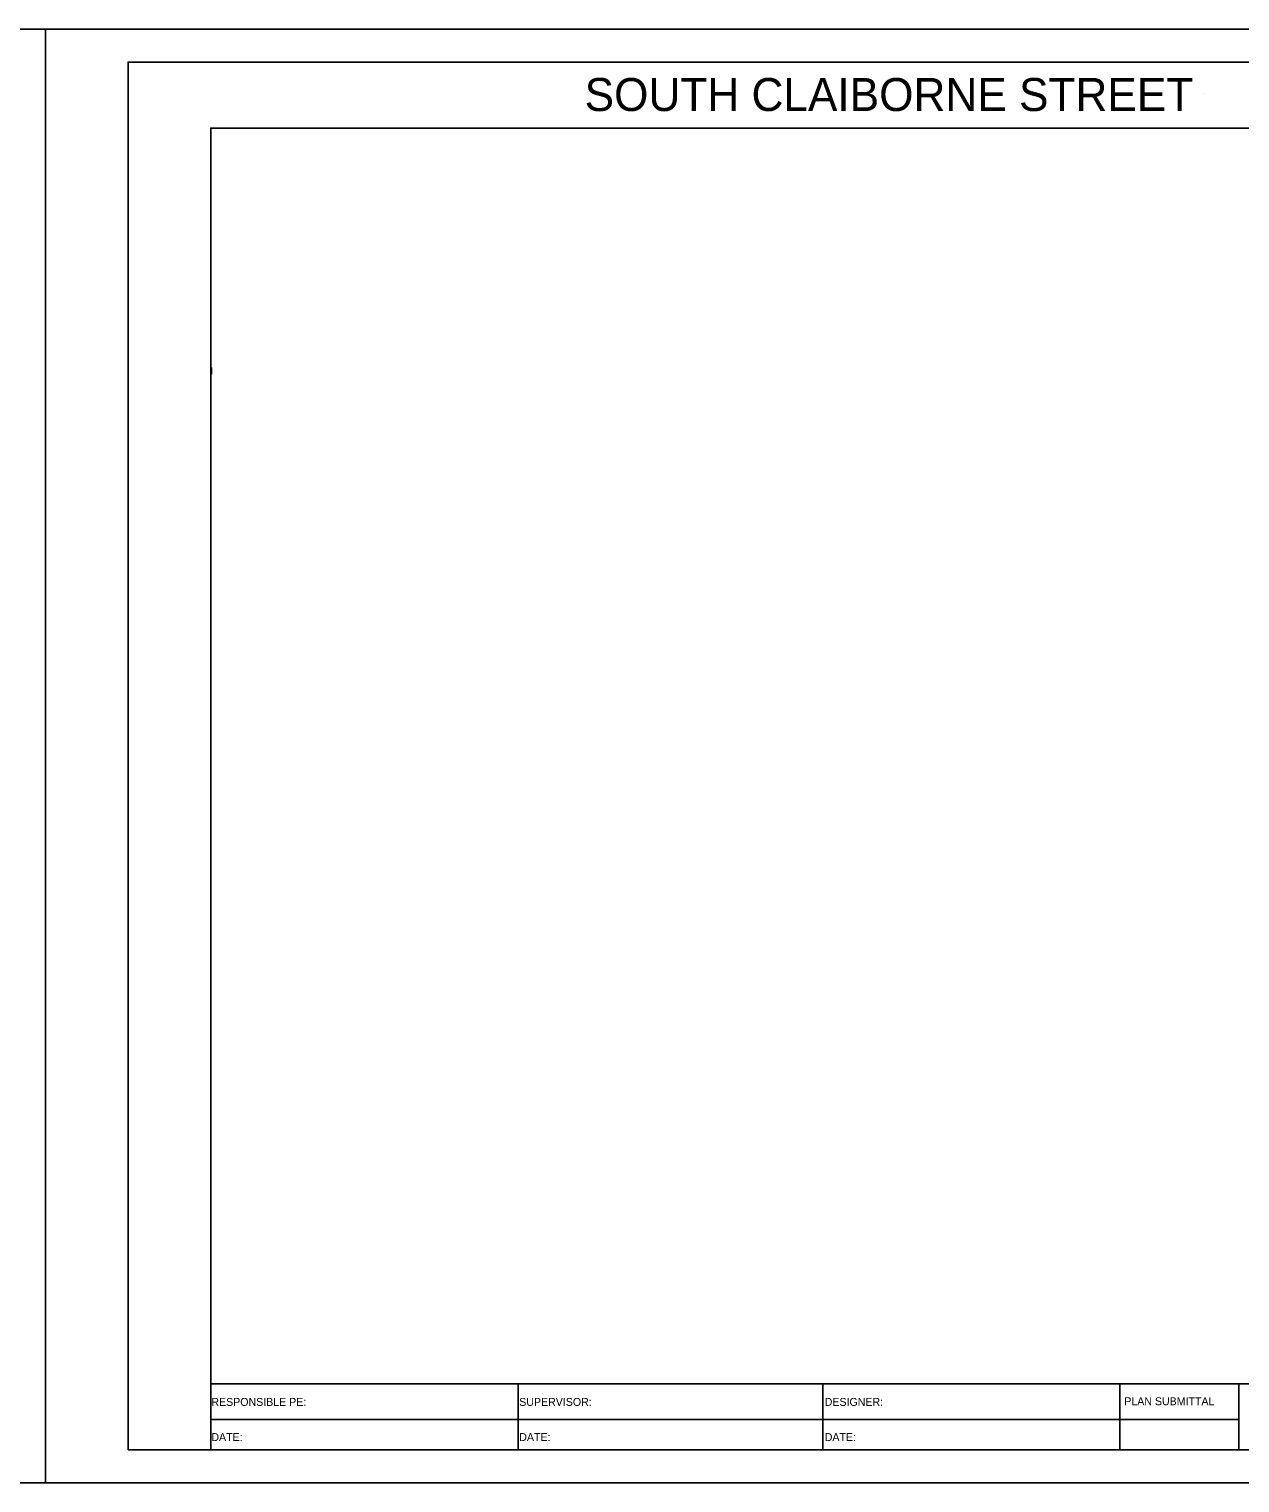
# Model space of a CAD drawing. Extents: x 1797478 to 1803816, y 246529 to 250952.
# Drawn here: x 1803133.5 to 1803316.8, y 250064.4 to 250284.4 of the extents above; entities that cross this region are included whole.
import ezdxf

# ---------------------------------------------------------------- set-up
doc = ezdxf.new("R2010")
doc.units = 0
for name, color, linetype in [('2', 7, 'Continuous'), ('ANNO-SHT', 7, 'Continuous'), ('ANNO-TXT', 7, 'Continuous'), ('AXIS', 7, 'Continuous'), ('DRAINAGE', 7, 'Continuous'), ('Level 1', 7, 'Continuous'), ('Level 62', 7, 'Continuous'), ('SHT-BDR', 7, 'Continuous'), ('SHT-BNDRY', 7, 'Continuous')]:
    doc.layers.add(name, color=color, linetype=linetype)

# ---------------------------------------------------------------- blocks, each defined once
blk = doc.blocks.new('SC47208')
at = {"layer": 'Level 1'}
blk.add_line((0, 0), (0, 0), dxfattribs=at)

msp = doc.modelspace()

# ---------------------------------------------------------------- linework, layer by layer
at = {"layer": '2'}
msp.add_lwpolyline([(1803161.12, 250233.21), (1803161.1, 250232.21)], dxfattribs=at)
msp.add_lwpolyline([(1803161.12, 250233.21), (1803161.1, 250232.21)], dxfattribs=at)
at = {"layer": 'AXIS'}
msp.add_line((1803161, 250189.42), (1803161, 250189.43), dxfattribs=at)
at = {"layer": 'Level 62'}
for points in [[(1802796, 250064.42), (1803136, 250064.42), (1803136, 250284.42), (1802796, 250284.42)], [(1803136, 250064.42), (1803476, 250064.42), (1803476, 250284.42), (1803136, 250284.42)]]:
    msp.add_lwpolyline(points, close=True, dxfattribs=at)
at = {"layer": 'SHT-BDR'}
msp.add_lwpolyline([(1803161, 250079.43), (1803461, 250079.43), (1803461, 250269.43), (1803161, 250269.43)], close=True, dxfattribs=at)
at = {"layer": 'SHT-BNDRY'}
for p, q in [((1803161, 250069.42), (1803161, 250079.43)), ((1803207.52, 250079.43), (1803207.52, 250069.42)), ((1803253.67, 250069.42), (1803253.67, 250079.43)), ((1803298.59, 250069.42), (1803298.59, 250079.43)), ((1803316.63, 250069.42), (1803316.63, 250079.43)), ((1803161, 250074.03), (1803316.63, 250074.03))]:
    msp.add_line(p, q, dxfattribs=at)
msp.add_lwpolyline([(1803148.5, 250069.42), (1803471, 250069.42), (1803471, 250279.42), (1803148.5, 250279.42)], close=True, dxfattribs=at)

# ---------------------------------------------------------------- block references
at = {"layer": 'DRAINAGE', "xscale": 0.2, "yscale": 0.20000000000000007, "rotation": -116.41666666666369}
msp.add_blockref('SC47208', (1803311.32, 250274.62), dxfattribs=at)
msp.add_blockref('SC47208', (1803311.32, 250274.62), dxfattribs=at)

# ---------------------------------------------------------------- texts
at = {"layer": 'ANNO-SHT'}
msp.add_text('         SOUTH CLAIBORNE STREET         ', height=4.9995, rotation=360, dxfattribs=at).set_placement((1803200.88, 250272.02))
at = {"layer": 'ANNO-TXT'}
for s, p in [('RESPONSIBLE PE:', (1803161.1, 250076.08)), ('SUPERVISOR:', (1803207.7, 250076.08)), ('DESIGNER:', (1803253.94, 250076.08)), ('PLAN SUBMITTAL', (1803299.28, 250076.18)), ('DATE:', (1803161.1, 250070.76)), ('DATE:', (1803207.7, 250070.76)), ('DATE:', (1803253.94, 250070.76))]:
    msp.add_text(s, height=1.2, rotation=360, dxfattribs=at).set_placement(p)

doc.saveas('drawing.dxf')
